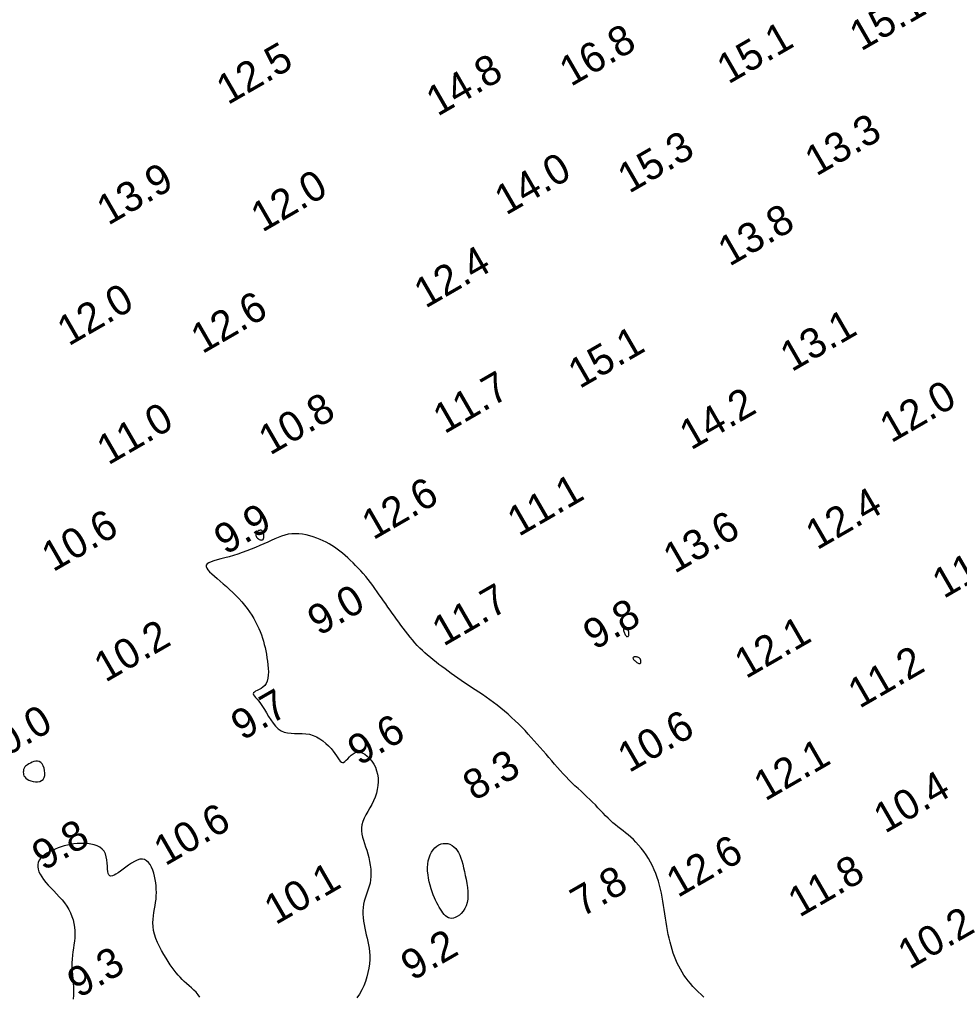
# Model space of a CAD drawing. Extents: x 3024098 to 3056816, y 418252 to 509144.
# Drawn here: x 3036950.5 to 3037107.7, y 419830.9 to 419994.1 of the extents above; entities that cross this region are included whole.
import ezdxf

# ---------------------------------------------------------------- set-up
doc = ezdxf.new("R2010")
doc.units = 0
doc.layers.add('V-CHAN-CONT-EL10', color=7, linetype='Continuous')
doc.layers.add('V-TOPO-SOUN-0911', color=7, linetype='Continuous')

msp = doc.modelspace()

# ---------------------------------------------------------------- linework, layer by layer
at = {"layer": 'V-CHAN-CONT-EL10'}
for points in [[(3037064.98, 419830.58), (3037064.51, 419831.03), (3037064.04, 419831.48), (3037063.59, 419831.93), (3037063.15, 419832.4), (3037062.74, 419832.86), (3037062.35, 419833.33), (3037061.99, 419833.8), (3037061.65, 419834.28), (3037061.33, 419834.77), (3037061.04, 419835.27), (3037060.77, 419835.78), (3037060.51, 419836.3), (3037060.27, 419836.84), (3037060.05, 419837.4), (3037059.84, 419837.98), (3037059.65, 419838.57), (3037059.48, 419839.18), (3037059.32, 419839.81), (3037059.17, 419840.45), (3037059.03, 419841.1), (3037058.9, 419841.77), (3037058.78, 419842.45), (3037058.67, 419843.14), (3037058.57, 419843.84), (3037058.46, 419844.54), (3037058.36, 419845.24), (3037058.25, 419845.94), (3037058.14, 419846.64), (3037058.02, 419847.33), (3037057.88, 419848.01), (3037057.74, 419848.68), (3037057.57, 419849.34), (3037057.39, 419850), (3037057.18, 419850.64), (3037056.94, 419851.28), (3037056.68, 419851.92), (3037056.38, 419852.55), (3037056.05, 419853.17), (3037055.69, 419853.79), (3037055.31, 419854.39), (3037054.91, 419854.96), (3037054.48, 419855.52), (3037054.05, 419856.04), (3037053.62, 419856.53), (3037053.18, 419856.98), (3037052.74, 419857.39), (3037052.31, 419857.76), (3037051.88, 419858.11), (3037051.46, 419858.43), (3037051.03, 419858.76), (3037050.61, 419859.08), (3037050.2, 419859.41), (3037049.78, 419859.76), (3037049.37, 419860.13), (3037048.96, 419860.53), (3037048.54, 419860.95), (3037048.13, 419861.39), (3037047.7, 419861.84), (3037047.27, 419862.3), (3037046.83, 419862.76), (3037046.37, 419863.22), (3037045.9, 419863.68), (3037045.42, 419864.13), (3037044.93, 419864.59), (3037044.43, 419865.05), (3037043.93, 419865.52), (3037043.42, 419865.98), (3037042.92, 419866.47), (3037042.42, 419866.96), (3037041.93, 419867.46), (3037041.45, 419867.97), (3037040.96, 419868.5), (3037040.49, 419869.03), (3037040.01, 419869.57), (3037039.54, 419870.12), (3037039.06, 419870.67), (3037038.58, 419871.23), (3037038.1, 419871.8), (3037037.61, 419872.36), (3037037.12, 419872.93), (3037036.62, 419873.49), (3037036.12, 419874.06), (3037035.6, 419874.62), (3037035.07, 419875.19), (3037034.52, 419875.75), (3037033.97, 419876.3), (3037033.4, 419876.85), (3037032.82, 419877.4), (3037032.23, 419877.93), (3037031.63, 419878.45), (3037031.02, 419878.95), (3037030.41, 419879.44), (3037029.8, 419879.91), (3037029.19, 419880.36), (3037028.57, 419880.8), (3037027.96, 419881.22), (3037027.35, 419881.62), (3037026.74, 419882.02), (3037026.14, 419882.41), (3037025.55, 419882.8), (3037024.96, 419883.18), (3037024.39, 419883.57), (3037023.83, 419883.96), (3037023.28, 419884.34), (3037022.74, 419884.73), (3037022.21, 419885.12), (3037021.69, 419885.51), (3037021.18, 419885.89), (3037020.68, 419886.27), (3037020.19, 419886.65), (3037019.71, 419887.03), (3037019.24, 419887.41), (3037018.79, 419887.8), (3037018.33, 419888.19), (3037017.9, 419888.6), (3037017.47, 419889.01), (3037017.04, 419889.44), (3037016.63, 419889.89), (3037016.23, 419890.35), (3037015.84, 419890.82), (3037015.45, 419891.31), (3037015.07, 419891.8), (3037014.69, 419892.31), (3037014.32, 419892.81), (3037013.95, 419893.32), (3037013.59, 419893.83), (3037013.23, 419894.34), (3037012.87, 419894.84), (3037012.5, 419895.35), (3037012.15, 419895.86), (3037011.79, 419896.38), (3037011.43, 419896.89), (3037011.07, 419897.4), (3037010.7, 419897.92), (3037010.34, 419898.43), (3037009.97, 419898.95), (3037009.6, 419899.46), (3037009.22, 419899.96), (3037008.83, 419900.47), (3037008.43, 419900.96), (3037008.03, 419901.45), (3037007.61, 419901.92), (3037007.18, 419902.39), (3037006.75, 419902.84), (3037006.31, 419903.28), (3037005.86, 419903.7), (3037005.42, 419904.11), (3037004.97, 419904.5), (3037004.53, 419904.87), (3037004.09, 419905.22), (3037003.66, 419905.55), (3037003.22, 419905.86), (3037002.77, 419906.16), (3037002.31, 419906.44), (3037001.83, 419906.7), (3037001.33, 419906.95), (3037000.8, 419907.18), (3037000.25, 419907.4), (3036999.67, 419907.6), (3036999.08, 419907.78), (3036998.47, 419907.92), (3036997.86, 419908.03), (3036997.25, 419908.1), (3036996.65, 419908.13), (3036996.06, 419908.1), (3036995.48, 419908.03), (3036994.92, 419907.9), (3036994.36, 419907.72), (3036993.8, 419907.51), (3036993.23, 419907.27), (3036992.65, 419907.01), (3036992.04, 419906.73), (3036991.4, 419906.44), (3036990.72, 419906.14), (3036990.02, 419905.84), (3036989.29, 419905.55), (3036988.55, 419905.26), (3036987.8, 419904.98), (3036987.06, 419904.72), (3036986.31, 419904.48), (3036985.59, 419904.27), (3036984.89, 419904.08), (3036984.22, 419903.91), (3036983.6, 419903.75), (3036983.05, 419903.6), (3036982.58, 419903.44), (3036982.2, 419903.28), (3036981.92, 419903.1), (3036981.77, 419902.89), (3036981.75, 419902.66), (3036981.85, 419902.39), (3036982.05, 419902.09), (3036982.34, 419901.77), (3036982.71, 419901.42), (3036983.14, 419901.04), (3036983.61, 419900.64), (3036984.11, 419900.21), (3036984.62, 419899.77), (3036985.15, 419899.3), (3036985.68, 419898.81), (3036986.2, 419898.31), (3036986.72, 419897.8), (3036987.22, 419897.27), (3036987.71, 419896.73), (3036988.17, 419896.19), (3036988.6, 419895.64), (3036989, 419895.08), (3036989.37, 419894.53), (3036989.71, 419893.97), (3036990.02, 419893.41), (3036990.3, 419892.85), (3036990.56, 419892.3), (3036990.79, 419891.76), (3036991, 419891.22), (3036991.18, 419890.68), (3036991.34, 419890.15), (3036991.48, 419889.61), (3036991.6, 419889.08), (3036991.72, 419888.53), (3036991.82, 419887.97), (3036991.91, 419887.39), (3036992, 419886.8), (3036992.08, 419886.2), (3036992.13, 419885.6), (3036992.15, 419885.02), (3036992.14, 419884.47), (3036992.08, 419883.96), (3036991.96, 419883.49), (3036991.79, 419883.09), (3036991.54, 419882.76), (3036991.25, 419882.48), (3036990.93, 419882.26), (3036990.6, 419882.08), (3036990.29, 419881.92), (3036990.02, 419881.79), (3036989.81, 419881.65), (3036989.68, 419881.51), (3036989.64, 419881.36), (3036989.69, 419881.18), (3036989.82, 419880.97), (3036990.02, 419880.72), (3036990.26, 419880.43), (3036990.55, 419880.09), (3036990.86, 419879.7), (3036991.19, 419879.24), (3036991.51, 419878.73), (3036991.85, 419878.16), (3036992.19, 419877.58), (3036992.56, 419876.99), (3036992.94, 419876.44), (3036993.35, 419875.93), (3036993.79, 419875.49), (3036994.27, 419875.16), (3036994.79, 419874.93), (3036995.35, 419874.8), (3036995.94, 419874.74), (3036996.54, 419874.73), (3036997.16, 419874.72), (3036997.79, 419874.72), (3036998.41, 419874.67), (3036999.02, 419874.57), (3036999.62, 419874.39), (3037000.2, 419874.13), (3037000.76, 419873.82), (3037001.28, 419873.46), (3037001.77, 419873.06), (3037002.22, 419872.64), (3037002.63, 419872.2), (3037002.99, 419871.77), (3037003.29, 419871.36), (3037003.56, 419870.97), (3037003.79, 419870.62), (3037003.99, 419870.32), (3037004.18, 419870.09), (3037004.36, 419869.93), (3037004.54, 419869.85), (3037004.73, 419869.88), (3037004.94, 419870.01), (3037005.17, 419870.22), (3037005.42, 419870.49), (3037005.7, 419870.78), (3037006, 419871.07), (3037006.32, 419871.32), (3037006.67, 419871.51), (3037007.04, 419871.6), (3037007.45, 419871.59), (3037007.86, 419871.46), (3037008.28, 419871.24), (3037008.7, 419870.93), (3037009.09, 419870.54), (3037009.46, 419870.1), (3037009.78, 419869.59), (3037010.05, 419869.05), (3037010.26, 419868.48), (3037010.4, 419867.88), (3037010.49, 419867.27), (3037010.51, 419866.64), (3037010.47, 419866), (3037010.37, 419865.35), (3037010.21, 419864.71), (3037010, 419864.08), (3037009.74, 419863.46), (3037009.43, 419862.85), (3037009.11, 419862.25), (3037008.78, 419861.66), (3037008.47, 419861.09), (3037008.2, 419860.53), (3037007.97, 419859.98), (3037007.81, 419859.44), (3037007.74, 419858.92), (3037007.74, 419858.4), (3037007.8, 419857.88), (3037007.91, 419857.36), (3037008.06, 419856.84), (3037008.23, 419856.3), (3037008.42, 419855.74), (3037008.6, 419855.17), (3037008.78, 419854.56), (3037008.94, 419853.94), (3037009.08, 419853.31), (3037009.19, 419852.67), (3037009.27, 419852.04), (3037009.31, 419851.42), (3037009.31, 419850.81), (3037009.26, 419850.23), (3037009.16, 419849.67), (3037009.02, 419849.15), (3037008.86, 419848.64), (3037008.68, 419848.14), (3037008.49, 419847.65), (3037008.32, 419847.16), (3037008.17, 419846.66), (3037008.05, 419846.14), (3037007.98, 419845.6), (3037007.95, 419845.05), (3037007.96, 419844.48), (3037008, 419843.91), (3037008.07, 419843.33), (3037008.17, 419842.75), (3037008.28, 419842.17), (3037008.4, 419841.6), (3037008.53, 419841.04), (3037008.67, 419840.48), (3037008.79, 419839.92), (3037008.91, 419839.36), (3037009, 419838.78), (3037009.07, 419838.18), (3037009.11, 419837.55), (3037009.1, 419836.89), (3037009.05, 419836.2), (3037008.96, 419835.47), (3037008.81, 419834.73), (3037008.62, 419833.98), (3037008.38, 419833.24), (3037008.1, 419832.51), (3037007.76, 419831.8), (3037007.39, 419831.13), (3037006.97, 419830.5)], [(3036980.7, 419830.58), (3036980.4, 419831), (3036980.06, 419831.41), (3036979.69, 419831.79), (3036979.29, 419832.16), (3036978.89, 419832.52), (3036978.49, 419832.88), (3036978.1, 419833.23), (3036977.73, 419833.57), (3036977.39, 419833.93), (3036977.06, 419834.3), (3036976.73, 419834.68), (3036976.41, 419835.1), (3036976.09, 419835.54), (3036975.76, 419836.02), (3036975.41, 419836.55), (3036975.05, 419837.13), (3036974.68, 419837.74), (3036974.31, 419838.39), (3036973.96, 419839.06), (3036973.64, 419839.75), (3036973.35, 419840.43), (3036973.13, 419841.12), (3036972.96, 419841.78), (3036972.87, 419842.42), (3036972.84, 419843.04), (3036972.87, 419843.64), (3036972.93, 419844.22), (3036973.02, 419844.79), (3036973.12, 419845.35), (3036973.22, 419845.91), (3036973.31, 419846.46), (3036973.37, 419847.01), (3036973.42, 419847.56), (3036973.43, 419848.11), (3036973.42, 419848.66), (3036973.38, 419849.2), (3036973.32, 419849.75), (3036973.23, 419850.29), (3036973.12, 419850.82), (3036972.98, 419851.35), (3036972.81, 419851.86), (3036972.6, 419852.34), (3036972.37, 419852.77), (3036972.11, 419853.13), (3036971.8, 419853.42), (3036971.46, 419853.61), (3036971.09, 419853.7), (3036970.67, 419853.66), (3036970.22, 419853.52), (3036969.75, 419853.3), (3036969.27, 419853.02), (3036968.79, 419852.7), (3036968.31, 419852.36), (3036967.85, 419852.02), (3036967.42, 419851.7), (3036967.03, 419851.42), (3036966.67, 419851.19), (3036966.35, 419851.01), (3036966.08, 419850.91), (3036965.84, 419850.87), (3036965.64, 419850.92), (3036965.49, 419851.06), (3036965.38, 419851.29), (3036965.31, 419851.63), (3036965.27, 419852.04), (3036965.25, 419852.52), (3036965.21, 419853.03), (3036965.15, 419853.56), (3036965.06, 419854.08), (3036964.9, 419854.58), (3036964.68, 419855.01), (3036964.37, 419855.38), (3036963.98, 419855.68), (3036963.53, 419855.91), (3036963.03, 419856.09), (3036962.49, 419856.21), (3036961.92, 419856.29), (3036961.34, 419856.32), (3036960.76, 419856.32), (3036960.19, 419856.29), (3036959.63, 419856.23), (3036959.08, 419856.14), (3036958.55, 419856.03), (3036958.02, 419855.89), (3036957.51, 419855.74), (3036957.01, 419855.56), (3036956.51, 419855.37), (3036956.03, 419855.15), (3036955.57, 419854.92), (3036955.13, 419854.68), (3036954.73, 419854.41), (3036954.38, 419854.13), (3036954.08, 419853.82), (3036953.85, 419853.5), (3036953.69, 419853.15), (3036953.6, 419852.79), (3036953.6, 419852.4), (3036953.67, 419852), (3036953.8, 419851.58), (3036954, 419851.15), (3036954.26, 419850.71), (3036954.58, 419850.26), (3036954.94, 419849.8), (3036955.35, 419849.34), (3036955.79, 419848.87), (3036956.26, 419848.4), (3036956.73, 419847.91), (3036957.2, 419847.41), (3036957.65, 419846.9), (3036958.08, 419846.37), (3036958.46, 419845.83), (3036958.8, 419845.27), (3036959.08, 419844.69), (3036959.31, 419844.1), (3036959.5, 419843.51), (3036959.64, 419842.91), (3036959.73, 419842.3), (3036959.79, 419841.71), (3036959.8, 419841.11), (3036959.77, 419840.53), (3036959.72, 419839.95), (3036959.65, 419839.37), (3036959.56, 419838.79), (3036959.48, 419838.2), (3036959.4, 419837.6), (3036959.35, 419836.98), (3036959.32, 419836.35), (3036959.32, 419835.69), (3036959.36, 419835.02), (3036959.41, 419834.33), (3036959.47, 419833.64), (3036959.52, 419832.94), (3036959.57, 419832.25), (3036959.59, 419831.58), (3036959.58, 419830.92), (3036959.53, 419830.28)]]:
    msp.add_lwpolyline(points, dxfattribs=at)
for points in [[(3036990.36, 419907.36), (3036990.49, 419907.26), (3036990.64, 419907.18), (3036990.79, 419907.11), (3036990.93, 419907.08), (3036991.07, 419907.07), (3036991.19, 419907.11), (3036991.29, 419907.18), (3036991.36, 419907.31), (3036991.41, 419907.48), (3036991.42, 419907.67), (3036991.41, 419907.87), (3036991.38, 419908.08), (3036991.33, 419908.27), (3036991.25, 419908.44), (3036991.16, 419908.58), (3036991.05, 419908.67), (3036990.93, 419908.71), (3036990.8, 419908.72), (3036990.67, 419908.69), (3036990.54, 419908.64), (3036990.42, 419908.56), (3036990.31, 419908.47), (3036990.22, 419908.37), (3036990.14, 419908.26), (3036990.09, 419908.15), (3036990.06, 419908.04), (3036990.04, 419907.93), (3036990.06, 419907.81), (3036990.1, 419907.7), (3036990.16, 419907.58), (3036990.25, 419907.47)], [(3037051.83, 419891.23), (3037051.91, 419891.12), (3037051.98, 419891.03), (3037052.06, 419890.96), (3037052.14, 419890.92), (3037052.21, 419890.9), (3037052.27, 419890.91), (3037052.33, 419890.95), (3037052.38, 419891.03), (3037052.41, 419891.13), (3037052.44, 419891.26), (3037052.44, 419891.4), (3037052.44, 419891.55), (3037052.42, 419891.7), (3037052.38, 419891.85), (3037052.32, 419891.99), (3037052.24, 419892.12), (3037052.15, 419892.22), (3037052.05, 419892.31), (3037051.94, 419892.37), (3037051.84, 419892.42), (3037051.74, 419892.43), (3037051.66, 419892.42), (3037051.6, 419892.37), (3037051.56, 419892.3), (3037051.54, 419892.2), (3037051.54, 419892.08), (3037051.56, 419891.94), (3037051.59, 419891.79), (3037051.64, 419891.64), (3037051.69, 419891.5), (3037051.76, 419891.36)], [(3037053.58, 419886.76), (3037053.68, 419886.67), (3037053.79, 419886.6), (3037053.9, 419886.53), (3037054.01, 419886.48), (3037054.11, 419886.44), (3037054.2, 419886.42), (3037054.27, 419886.41), (3037054.33, 419886.43), (3037054.38, 419886.46), (3037054.41, 419886.51), (3037054.43, 419886.58), (3037054.44, 419886.65), (3037054.44, 419886.73), (3037054.44, 419886.81), (3037054.43, 419886.89), (3037054.41, 419886.97), (3037054.4, 419887.05), (3037054.37, 419887.12), (3037054.33, 419887.19), (3037054.29, 419887.26), (3037054.23, 419887.32), (3037054.15, 419887.37), (3037054.06, 419887.42), (3037053.95, 419887.46), (3037053.83, 419887.49), (3037053.7, 419887.51), (3037053.58, 419887.52), (3037053.45, 419887.52), (3037053.34, 419887.51), (3037053.25, 419887.48), (3037053.18, 419887.45), (3037053.14, 419887.4), (3037053.12, 419887.34), (3037053.14, 419887.27), (3037053.17, 419887.19), (3037053.22, 419887.11), (3037053.29, 419887.02), (3037053.38, 419886.93), (3037053.47, 419886.84)], [(3036954.67, 419867.34), (3036954.76, 419867.7), (3036954.79, 419868.1), (3036954.75, 419868.52), (3036954.65, 419868.93), (3036954.5, 419869.31), (3036954.31, 419869.64), (3036954.09, 419869.88), (3036953.83, 419870.03), (3036953.54, 419870.09), (3036953.25, 419870.08), (3036952.94, 419870.01), (3036952.65, 419869.9), (3036952.37, 419869.77), (3036952.11, 419869.62), (3036951.89, 419869.48), (3036951.71, 419869.35), (3036951.57, 419869.23), (3036951.46, 419869.13), (3036951.37, 419869.03), (3036951.31, 419868.93), (3036951.27, 419868.82), (3036951.23, 419868.7), (3036951.21, 419868.56), (3036951.19, 419868.41), (3036951.18, 419868.23), (3036951.19, 419868.04), (3036951.22, 419867.85), (3036951.29, 419867.65), (3036951.41, 419867.45), (3036951.58, 419867.26), (3036951.81, 419867.08), (3036952.1, 419866.92), (3036952.44, 419866.79), (3036952.81, 419866.69), (3036953.2, 419866.64), (3036953.58, 419866.64), (3036953.94, 419866.7), (3036954.25, 419866.83), (3036954.5, 419867.04)], [(3037018.9, 419853.39), (3037019.04, 419853.92), (3037019.23, 419854.41), (3037019.45, 419854.85), (3037019.71, 419855.25), (3037020.01, 419855.6), (3037020.33, 419855.88), (3037020.67, 419856.1), (3037021.03, 419856.25), (3037021.4, 419856.32), (3037021.78, 419856.33), (3037022.15, 419856.28), (3037022.51, 419856.17), (3037022.86, 419855.99), (3037023.19, 419855.77), (3037023.48, 419855.48), (3037023.74, 419855.15), (3037023.96, 419854.78), (3037024.16, 419854.35), (3037024.34, 419853.88), (3037024.5, 419853.38), (3037024.65, 419852.83), (3037024.79, 419852.25), (3037024.94, 419851.63), (3037025.08, 419850.98), (3037025.21, 419850.32), (3037025.33, 419849.64), (3037025.43, 419848.96), (3037025.49, 419848.29), (3037025.51, 419847.63), (3037025.48, 419847.01), (3037025.38, 419846.43), (3037025.22, 419845.9), (3037025, 419845.42), (3037024.72, 419844.99), (3037024.42, 419844.62), (3037024.09, 419844.32), (3037023.75, 419844.08), (3037023.41, 419843.9), (3037023.09, 419843.8), (3037022.79, 419843.76), (3037022.51, 419843.79), (3037022.25, 419843.88), (3037022.01, 419844.02), (3037021.78, 419844.21), (3037021.56, 419844.44), (3037021.35, 419844.7), (3037021.14, 419844.99), (3037020.93, 419845.3), (3037020.72, 419845.64), (3037020.52, 419846), (3037020.31, 419846.38), (3037020.12, 419846.8), (3037019.92, 419847.24), (3037019.73, 419847.71), (3037019.55, 419848.21), (3037019.37, 419848.75), (3037019.21, 419849.31), (3037019.06, 419849.89), (3037018.94, 419850.48), (3037018.85, 419851.08), (3037018.79, 419851.68), (3037018.78, 419852.27), (3037018.82, 419852.84)]]:
    msp.add_lwpolyline(points, close=True, dxfattribs=at)

# ---------------------------------------------------------------- texts
at = {"layer": 'V-TOPO-SOUN-0911'}
for s, p in [('15.1 ', (3037091.24, 419988.77)), ('16.8 ', (3037042.73, 419982.85)), ('15.1 ', (3037069.06, 419983.25)), ('12.5 ', (3036985.37, 419979.79)), ('14.8 ', (3037020.45, 419977.86)), ('13.3 ', (3037083.77, 419967.85)), ('15.3 ', (3037052.47, 419964.97)), ('14.0 ', (3037031.89, 419961.32)), ('13.9 ', (3036965.37, 419959.62)), ('12.0 ', (3036991.14, 419958.47)), ('13.8 ', (3037069.24, 419952.76)), ('12.4 ', (3037018.42, 419945.74)), ('12.0 ', (3036958.76, 419939.44)), ('12.6 ', (3036981.11, 419938.13)), ('13.1 ', (3037079.65, 419935.12)), ('15.1 ', (3037044.19, 419932.3)), ('11.7 ', (3037021.6, 419924.74)), ('12.0 ', (3037096.29, 419923.23)), ('14.2 ', (3037062.81, 419922.02)), ('10.8 ', (3036992.43, 419921.17)), ('11.0 ', (3036965.38, 419919.52)), ('12.6 ', (3037009.69, 419907)), ('11.1 ', (3037034.02, 419907.57)), ('12.4 ', (3037083.9, 419905.32)), ('10.6 ', (3036956.15, 419901.65)), ('9.9', (3036984.99, 419904.51)), ('13.6 ', (3037060.08, 419901.39)), ('11.3 ', (3037105.07, 419897.18)), ('9.0', (3037000.62, 419890.95)), ('11.7 ', (3037021.44, 419889.21)), ('9.8', (3037046.7, 419888.59)), ('10.2 ', (3036964.91, 419883.17)), ('12.1 ', (3037072.01, 419883.78)), ('11.2 ', (3037090.99, 419878.81)), ('9.7', (3036987.81, 419873.44)), ('10.0 ', (3036945.14, 419868.93)), ('9.6', (3037007.33, 419869.24)), ('10.6 ', (3037052.47, 419868.06)), ('12.1 ', (3037075.23, 419863.31)), ('8.3', (3037026.59, 419863.33)), ('10.4 ', (3037095.26, 419857.91)), ('10.6 ', (3036974.91, 419852.47)), ('9.8', (3036954.54, 419851.65)), ('12.6 ', (3037060.61, 419847.16)), ('11.8 ', (3037080.95, 419843.87)), ('10.1 ', (3036993.37, 419842.61)), ('7.8', (3037044.57, 419843.91)), ('10.2 ', (3037099.32, 419835.14)), ('9.2', (3037016.22, 419833.25)), ('9.3', (3036960.45, 419830.36))]:
    msp.add_text(s, height=5, rotation=30, dxfattribs=at).set_placement(p)

doc.saveas('drawing.dxf')
